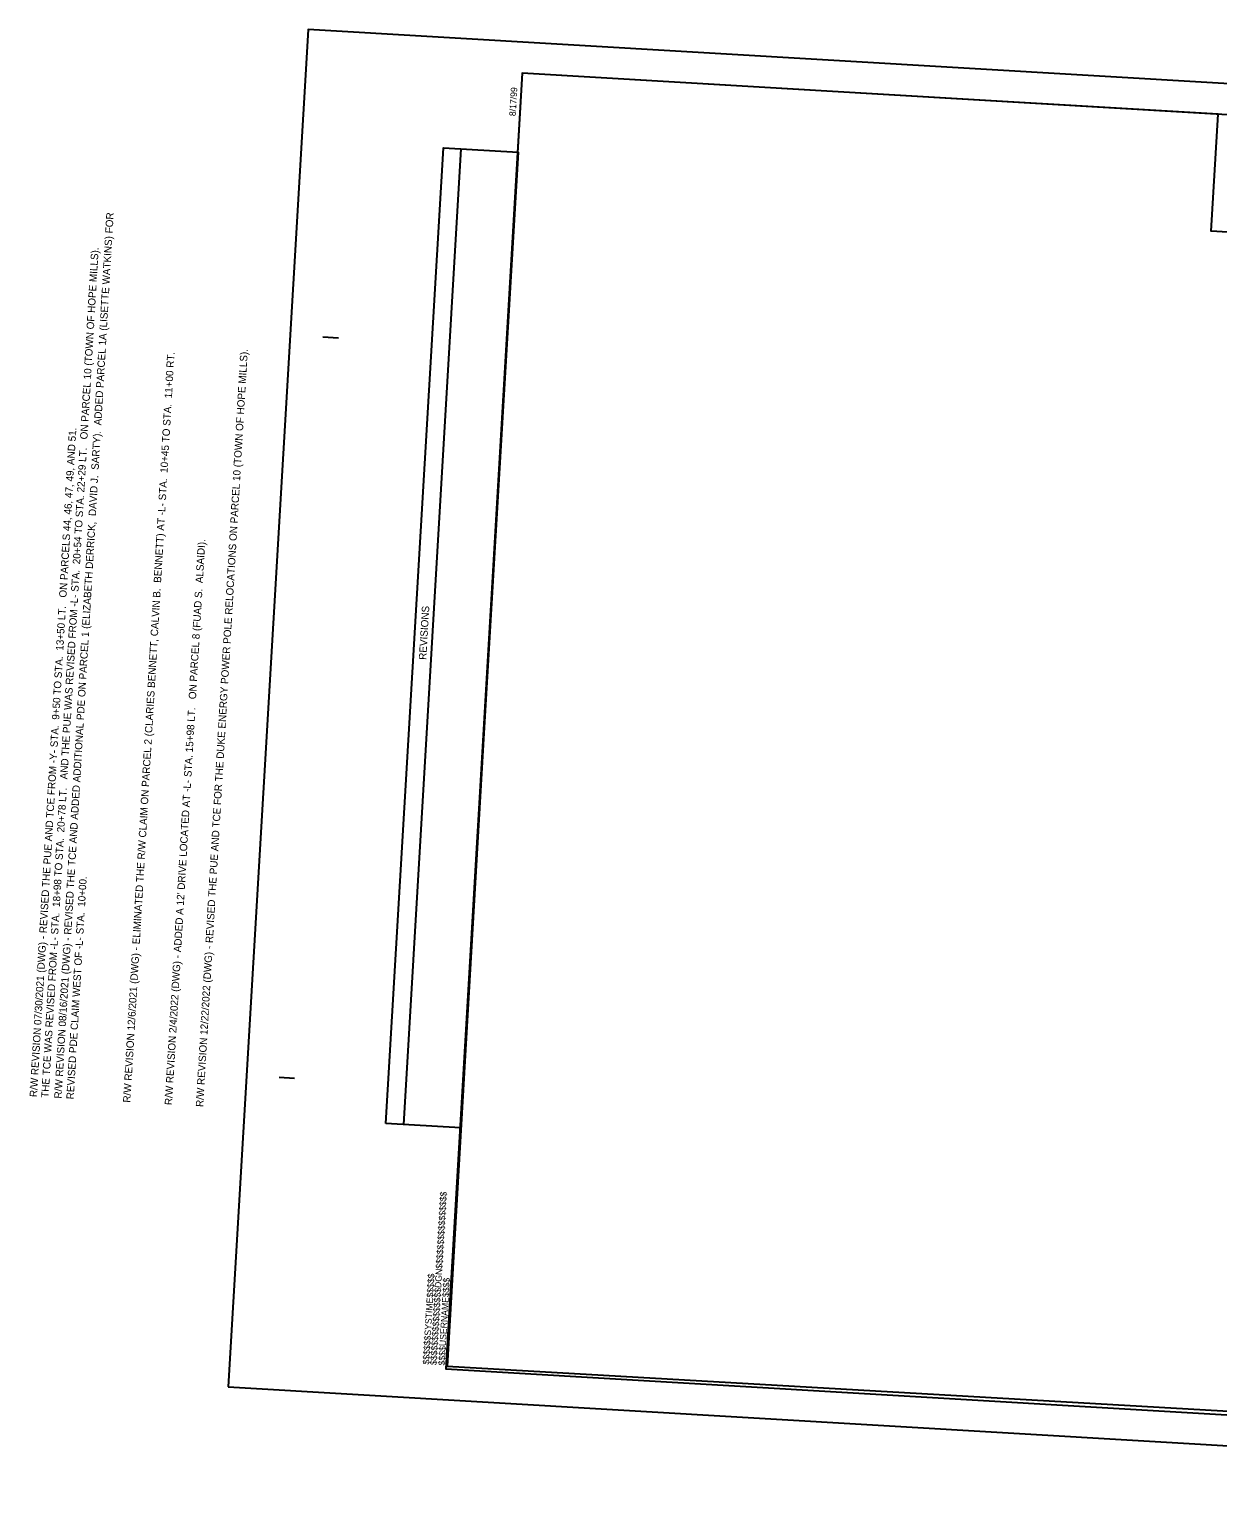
# Model space of a CAD drawing. Extents: x 2010810 to 2012732, y 444258 to 445456.
# Drawn here: x 2010810 to 2011771, y 444258 to 445456 of the extents above; entities that cross this region are included whole.
import ezdxf

# ---------------------------------------------------------------- set-up
doc = ezdxf.new("R2010")
doc.units = 0
for name, color, linetype in [('Old_Level_1', 7, 'Continuous'), ('Sheet Block Revision CELL', 7, 'Continuous'), ('Sheet Block System Information CELL', 7, 'Continuous'), ('Sheet Clip Boundary CELL', 7, 'Continuous'), ('Sheet Plan And Profile CELL', 7, 'Continuous'), ('Sheet Plot Border Outside CELL', 7, 'Continuous')]:
    doc.layers.add(name, color=color, linetype=linetype)

msp = doc.modelspace()

# ---------------------------------------------------------------- linework, layer by layer
at = {"layer": 'Sheet Block Revision CELL'}
msp.add_line((2011112.7, 444570.6), (2011159.2, 445359.8), dxfattribs=at)
msp.add_lwpolyline([(2011098.2, 444571.4), (2011144.7, 445360.7), (2011205.1, 445357.1), (2011158.6, 444567.9)], close=True, dxfattribs=at)
at = {"layer": 'Sheet Block System Information CELL'}
msp.add_line((2011146.7, 444372.9), (2011146.7, 444372.9), dxfattribs=at)
at = {"layer": 'Sheet Clip Boundary CELL'}
msp.add_lwpolyline([(2012177, 445268.5), (2011766, 445293.2), (2011771.6, 445387.9), (2011477.9, 445405.2), (2011208.5, 445421.1), (2011200.1, 445278.3), (2011147.8, 444375), (2012145.7, 444317.5)], dxfattribs=at)
at = {"layer": 'Sheet Plan And Profile CELL'}
for p, q in [((2011047.2, 445207.7), (2011059.7, 445207)), ((2011011.9, 444608.8), (2011024.3, 444608)), ((2011146.7, 444372.9), (2011146.7, 444372.9)), ((2011146.7, 444372.9), (2011146.7, 444372.9)), ((2011146.7, 444372.9), (2011146.7, 444372.9)), ((2011146.7, 444372.9), (2011146.7, 444372.9)), ((2011146.7, 444372.9), (2011146.7, 444372.9))]:
    msp.add_line(p, q, dxfattribs=at)
msp.add_lwpolyline([(2012705.9, 445332.8), (2011208.5, 445421.1), (2011146.7, 444372.9), (2012644.1, 444284.7)], close=True, dxfattribs=at)
at = {"layer": 'Sheet Plot Border Outside CELL'}
msp.add_lwpolyline([(2010970.6, 444358.3), (2012667.6, 444258.2), (2012732.3, 445356.3), (2011035.3, 445456.4)], close=True, dxfattribs=at)

# ---------------------------------------------------------------- texts
at = {"layer": 'Old_Level_1'}
for s, p in [('R/W REVISION 08/16/2021 (DWG) - REVISED THE TCE AND ADDED ADDITIONAL PDE ON PARCEL 1 (ELIZABETH DERRICK,  DAVID J.  SARTY).  ADDED PARCEL 1A (LISETTE WATKINS) FOR   ', (2010835.7, 444591.3)), ('THE TCE WAS REVISED FROM -L- STA.  18+98 TO STA.  20+78 LT.   AND THE PUE WAS REVISED FROM -L- STA.  20+54 TO STA. 22+29 LT.   ON PARCEL 10 (TOWN OF HOPE MILLS). ', (2010825.2, 444591.9)), ('R/W REVISION 12/6/2021 (DWG) - ELIMINATED THE R/W CLAIM ON PARCEL 2 (CLARIES BENNETT, CALVIN B.  BENNETT) AT -L- STA.  10+45 TO STA.  11+00 RT. ', (2010891.4, 444588)), ('R/W REVISION 12/22/2022 (DWG) - REVISED THE PUE AND TCE FOR THE DUKE ENERGY POWER POLE RELOCATIONS ON PARCEL 10 (TOWN OF HOPE MILLS).', (2010950.3, 444584.5)), ('R/W REVISION 07/30/2021 (DWG) - REVISED THE PUE AND TCE FROM -Y- STA.  9+50 TO STA.  13+50 LT.   ON PARCELS 44, 46, 47, 49, AND 51. ', (2010815.8, 444592.5)), ("R/W REVISION 2/4/2022 (DWG) - ADDED A 12' DRIVE LOCATED AT -L- STA. 15+98 LT.   ON PARCEL 8 (FUAD S.  ALSAIDI).", (2010925.1, 444586)), ('REVISED PDE CLAIM WEST OF -L- STA.  10+00. ', (2010845.5, 444590.7))]:
    msp.add_text(s, height=6, rotation=86.6264, dxfattribs=at).set_placement(p)
at = {"layer": 'Sheet Block Revision CELL'}
msp.add_text('REVISIONS', height=6, rotation=86.6264, dxfattribs=at).set_placement((2011130.8, 444946.3))
at = {"layer": 'Sheet Block System Information CELL'}
for s, p in [('$$$$$$$$$$$$$$$$DGN$$$$$$$$$$$$$$$$', (2011139.2, 444375.7)), ('$$$$$$SYSTIME$$$$$', (2011133.2, 444376.1)), ('$$$$USERNAME$$$$', (2011145.8, 444375.4))]:
    msp.add_text(s, height=5.25, rotation=86.6264, dxfattribs=at).set_placement(p)
at = {"layer": 'Sheet Plan And Profile CELL'}
msp.add_text('8/17/99', height=5.25, rotation=86.6264, dxfattribs=at).set_placement((2011203.2, 445386.2))

doc.saveas('drawing.dxf')
